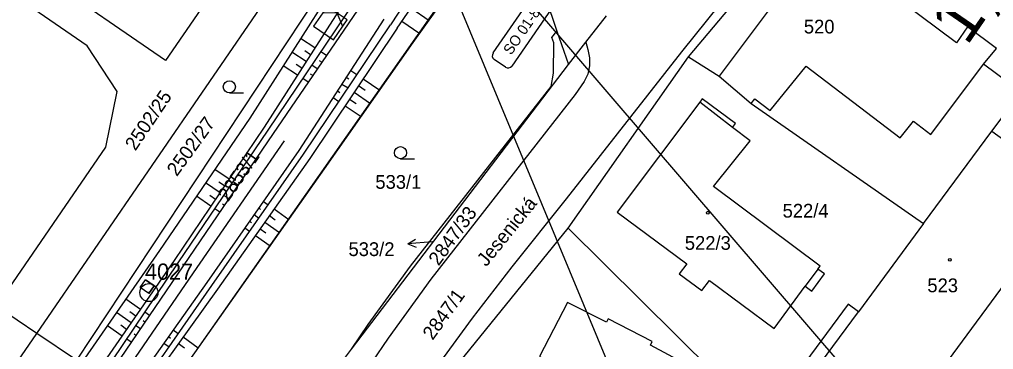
# Model space of a CAD drawing. Extents: x -558358 to -557517, y -1073786 to -1073189.
# Drawn here: x -558199.4 to -558078.9, y -1073467.9 to -1073427.1 of the extents above; entities that cross this region are included whole.
import ezdxf

# ---------------------------------------------------------------- set-up
doc = ezdxf.new("R2010")
doc.units = 0
for name, color, linetype in [('Body', 7, 'Continuous'), ('Hranice parcel', 7, 'Continuous'), ('Kolej', 7, 'Continuous'), ('Křížky', 7, 'Continuous'), ('Lomové body_krizky', 7, 'Continuous'), ('Návěst místo trati', 7, 'Continuous'), ('Parcelní čísla', 7, 'Continuous'), ('Plot - zábradlí', 7, 'Continuous'), ('Pop  PČ popisy', 7, 'Continuous'), ('Přejezd - štěrkové lože', 7, 'Continuous'), ('Sonda - šrafa - vrstevnice', 7, 'Continuous'), ('Svazek obcí údolí Desné', 7, 'Continuous'), ('Vnitřní kresba', 7, 'Continuous'), ('Vrstva 1', 7, 'Continuous'), ('Vrstva 28', 7, 'Continuous'), ('Vrstva 60', 7, 'Continuous'), ('Značky budov', 7, 'Continuous'), ('Značky kultur', 7, 'Continuous')]:
    doc.layers.add(name, color=color, linetype=linetype)

msp = doc.modelspace()

# ---------------------------------------------------------------- linework, layer by layer
at = {"layer": 'Body'}
for p, q in [((-558182.76, -1073460), (-558183.81, -1073459.27)), ((-558183.41, -1073460.95), (-558184.47, -1073460.2))]:
    msp.add_line(p, q, dxfattribs=at)
for points in [[(-558182.76, -1073460), (-558183.41, -1073460.95), (-558184.47, -1073460.2), (-558183.81, -1073459.27), (-558182.76, -1073460)], [(-558184.47, -1073460.2), (-558184.47, -1073460.2), (-558183.81, -1073459.27), (-558183.81, -1073459.27)], [(-558183.41, -1073460.95), (-558183.41, -1073460.95), (-558182.76, -1073460), (-558182.76, -1073460)]]:
    msp.add_lwpolyline(points, dxfattribs=at)
at = {"layer": 'Hranice parcel'}
for p, q in [((-558116.63, -1073431.7), (-558081, -1073389.4)), ((-558138.47, -1073412.32), (-558132.91, -1073428.56)), ((-558197.28, -1073465.89), (-558161.06, -1073413.25)), ((-558100.23, -1073417.28), (-558112.83, -1073434.1)), ((-558129.35, -1073429.91), (-558126.8, -1073426.64)), ((-558133.56, -1073429.34), (-558132.91, -1073428.56)), ((-558132.91, -1073428.56), (-558131.5, -1073432.67)), ((-558131.5, -1073432.67), (-558129.35, -1073429.91)), ((-558129.35, -1073429.91), (-558129.07, -1073430.81)), ((-558131.54, -1073452.88), (-558116.63, -1073431.7)), ((-558116.63, -1073431.7), (-558112.83, -1073434.1)), ((-558158.31, -1073467.84), (-558131.5, -1073432.67)), ((-558087.54, -1073452.3), (-558079.09, -1073440.91)), ((-558079.09, -1073440.91), (-558069.01, -1073448.19)), ((-558087.54, -1073452.3), (-558095.61, -1073463.24)), ((-558111.36, -1073472.82), (-558131.54, -1073452.88)), ((-558197.28, -1073465.89), (-558202.26, -1073462.53)), ((-558158.31, -1073467.84), (-558156.26, -1073464.79)), ((-558192.36, -1073469.21), (-558197.28, -1073465.89)), ((-558164.08, -1073475.42), (-558158.31, -1073467.84))]:
    msp.add_line(p, q, dxfattribs=at)
for points in [[(-558086.19, -1073392.25), (-558100.56, -1073410.01), (-558117.51, -1073431.08), (-558131.78, -1073449.27), (-558138.48, -1073457.68), (-558143.38, -1073464.02), (-558146.99, -1073468.89), (-558150.46, -1073473.83), (-558152.02, -1073476.41), (-558154.26, -1073480.97), (-558156.46, -1073486.6), (-558158.91, -1073494.31), (-558160.3, -1073500.48), (-558162.16, -1073510.4), (-558165.76, -1073536.46), (-558169.94, -1073565.43), (-558173.74, -1073591.61), (-558177.66, -1073620.33), (-558178.51, -1073631.87), (-558179.02, -1073643), (-558179.24, -1073655.12), (-558179.45, -1073666.94), (-558179.49, -1073675.4)], [(-558166.05, -1073409.92), (-558181.36, -1073432.16), (-558196.71, -1073421.6)], [(-558202.26, -1073462.53), (-558188.73, -1073442.87), (-558187.31, -1073436.01), (-558191.04, -1073430.36), (-558216.02, -1073413.17)], [(-558079.09, -1073440.91), (-558075.49, -1073436.06), (-558080.13, -1073432.64), (-558078.53, -1073430.7), (-558082.12, -1073428.01), (-558083.47, -1073429.99), (-558090.26, -1073424.91), (-558087.3, -1073420.92), (-558091.08, -1073418.03), (-558093.98, -1073421.97), (-558100.23, -1073417.28)], [(-558156.26, -1073464.79), (-558151.01, -1073457.58), (-558133.63, -1073435.37), (-558133.35, -1073433.74), (-558133.31, -1073429.98), (-558133.56, -1073429.34)], [(-558129.07, -1073430.81), (-558128.89, -1073431.83), (-558128.89, -1073432.84), (-558129.1, -1073433.85), (-558129.56, -1073434.77), (-558130.67, -1073436.36), (-558148.52, -1073459.19), (-558153.8, -1073466.46), (-558155.8, -1073469.46), (-558158.84, -1073474.63), (-558161.5, -1073480.01), (-558162.64, -1073482.78), (-558164.73, -1073488.39)], [(-558112.83, -1073434.1), (-558108.9, -1073437.49), (-558087.54, -1073452.3)], [(-558115.24, -1073437.31), (-558125.46, -1073450.9), (-558116.85, -1073457.27), (-558117.77, -1073458.51), (-558114.97, -1073460.58), (-558114.05, -1073459.35), (-558106.05, -1073465.28), (-558102.2, -1073460.05)], [(-558110.8, -1073439.94), (-558114.93, -1073436.89), (-558115.24, -1073437.31)], [(-558100.63, -1073457.93), (-558100.36, -1073457.56), (-558113.55, -1073447.75), (-558109, -1073442.11), (-558111.2, -1073440.45), (-558110.8, -1073439.94)], [(-558069.01, -1073448.19), (-558089.39, -1073475.8), (-558089.17, -1073475.95), (-558090.09, -1073477.27), (-558100.29, -1073469.58), (-558095.61, -1073463.24)], [(-558151.25, -1073481.61), (-558144.94, -1073469.39), (-558131.54, -1073452.88)], [(-558102.2, -1073460.05), (-558101.38, -1073460.67), (-558099.8, -1073458.54), (-558100.63, -1073457.93)], [(-558111.36, -1073472.82), (-558111.67, -1073473.41), (-558117.43, -1073469.44), (-558121.34, -1073467.34), (-558121.11, -1073466.9), (-558126.57, -1073464.07), (-558126.8, -1073464.51), (-558131.6, -1073462.08), (-558135.08, -1073468.74), (-558134.91, -1073468.83), (-558142.45, -1073483.25), (-558143.96, -1073486.09)], [(-558095.61, -1073463.24), (-558096.89, -1073462.29), (-558107.49, -1073476.62)], [(-558235.03, -1073522.1), (-558231.61, -1073515.78), (-558197.28, -1073465.89)]]:
    msp.add_lwpolyline(points, dxfattribs=at)
at = {"layer": 'Kolej'}
msp.add_lwpolyline([(-558222.5, -1073523.52), (-558211.35, -1073507.26), (-558189.16, -1073474.89), (-558177.86, -1073458.42), (-558166.63, -1073442.09)], dxfattribs=at)
at = {"layer": 'Křížky'}
for points in [[(-558140.82, -1073431.24), (-558135.04, -1073422.86)], [(-558132.71, -1073424.46), (-558138.49, -1073432.85)], [(-558139.28, -1073432.99), (-558140.67, -1073432.03)]]:
    msp.add_lwpolyline(points, dxfattribs=at)
for centre, start, end in [((-558140.35, -1073431.57), 145.4427, 235.4427), ((-558138.96, -1073432.53), 235.4427, 325.4427)]:
    msp.add_arc(centre, 0.566, start, end, dxfattribs=at)
at = {"layer": 'Lomové body_krizky'}
for points in [[(-558152.7, -1073428.17), (-558144.23, -1073415.84), (-558139.35, -1073410.55), (-558136.98, -1073416.27)], [(-558160.27, -1073422.61), (-558170.92, -1073439.28), (-558182.07, -1073455.63), (-558193.45, -1073472.04), (-558204.95, -1073487.53), (-558215.83, -1073504.11), (-558218.74, -1073509.41), (-558221.47, -1073511.54)], [(-558158.61, -1073423.97), (-558169.15, -1073440.42), (-558180.26, -1073456.88), (-558191.27, -1073472.78), (-558202.46, -1073489.11), (-558213.8, -1073505.71), (-558218.06, -1073510.9), (-558220.02, -1073511.36), (-558220.66, -1073512.06)], [(-558152.7, -1073428.17), (-558163.49, -1073444.26), (-558174.92, -1073460.4), (-558186.51, -1073476.58), (-558197.24, -1073492.86), (-558208.77, -1073509.05), (-558219.85, -1073525.27), (-558227.1, -1073535.75), (-558230.39, -1073540.52), (-558231, -1073543.03)]]:
    msp.add_lwpolyline(points, dxfattribs=at)
at = {"layer": 'Návěst místo trati'}
for points in [[(-558160.09, -1073426.3), (-558161.32, -1073425.45), (-558163.02, -1073427.92), (-558160.55, -1073429.62), (-558158.85, -1073427.15), (-558160.09, -1073426.3)], [(-558159.42, -1073427.97), (-558160.09, -1073426.3), (-558161.89, -1073426.27)]]:
    msp.add_lwpolyline(points, dxfattribs=at)
at = {"layer": 'Plot - zábradlí'}
for points in [[(-558150.68, -1073429.95), (-558139.41, -1073414.15), (-558135.83, -1073423.84)], [(-558226.6, -1073552.39), (-558229.62, -1073542.12), (-558228.84, -1073541.34), (-558220.94, -1073529.81), (-558210.66, -1073515.21), (-558195.56, -1073493.62), (-558184.31, -1073477.57), (-558177.73, -1073468.27), (-558161.67, -1073445.55), (-558150.68, -1073429.95)]]:
    msp.add_lwpolyline(points, dxfattribs=at)
at = {"layer": 'Pop  PČ popisy'}
for p, q in [((-558151.36, -1073454.83), (-558150.41, -1073454.25)), ((-558148.37, -1073454.57), (-558151.36, -1073454.83)), ((-558151.36, -1073454.83), (-558150.32, -1073455.24))]:
    msp.add_line(p, q, dxfattribs=at)
at = {"layer": 'Přejezd - štěrkové lože'}
for p, q in [((-558161.43, -1073431.55), (-558162.11, -1073431.09)), ((-558162.56, -1073433.2), (-558163.23, -1073432.75)), ((-558162, -1073432.38), (-558162.27, -1073432.19)), ((-558163.13, -1073434.02), (-558163.39, -1073433.84)), ((-558158.97, -1073434.24), (-558158.67, -1073434.44)), ((-558158.43, -1073433.4), (-558157.65, -1073433.91)), ((-558163.69, -1073434.85), (-558164.35, -1073434.4)), ((-558159.52, -1073435.08), (-558158.76, -1073435.56)), ((-558160.06, -1073435.92), (-558159.77, -1073436.11)), ((-558160.61, -1073436.75), (-558159.88, -1073437.23)), ((-558172.38, -1073447.59), (-558172.99, -1073447.17)), ((-558172.94, -1073448.42), (-558173.19, -1073448.25)), ((-558174.06, -1073450.07), (-558174.31, -1073449.91)), ((-558173.5, -1073449.24), (-558174.11, -1073448.83)), ((-558169.23, -1073449.57), (-558168.64, -1073449.99)), ((-558174.62, -1073450.9), (-558175.23, -1073450.48)), ((-558169.81, -1073450.39), (-558169.57, -1073450.56)), ((-558170.95, -1073452.03), (-558170.71, -1073452.2)), ((-558170.38, -1073451.21), (-558169.78, -1073451.63)), ((-558171.52, -1073452.85), (-558170.93, -1073453.27)), ((-558183.88, -1073464.5), (-558184.11, -1073464.34)), ((-558183.32, -1073463.67), (-558183.9, -1073463.28)), ((-558184.45, -1073465.32), (-558185.02, -1073464.93)), ((-558180.39, -1073465.46), (-558179.76, -1073465.91)), ((-558185.58, -1073466.97), (-558186.14, -1073466.59)), ((-558185.01, -1073466.15), (-558185.24, -1073465.99)), ((-558180.96, -1073466.27), (-558180.71, -1073466.46)), ((-558181.54, -1073467.09), (-558180.9, -1073467.54))]:
    msp.add_line(p, q, dxfattribs=at)
for points in [[(-558140.88, -1073407.43), (-558141.3, -1073409.14), (-558145.29, -1073415.26), (-558153.52, -1073427.77)], [(-558233.12, -1073536.27), (-558231.44, -1073532.59), (-558224.31, -1073522.11), (-558213.32, -1073506.02), (-558201.98, -1073489.48), (-558190.68, -1073473.3), (-558179.76, -1073457.16), (-558168.65, -1073440.76), (-558157.79, -1073424.72)], [(-558157.06, -1073425.16), (-558168.03, -1073441.18), (-558179.14, -1073457.55), (-558190.46, -1073474.12), (-558201.29, -1073490), (-558212.69, -1073506.36), (-558223.92, -1073522.5), (-558230.65, -1073533.02), (-558233.12, -1073536.27)], [(-558154.33, -1073427.06), (-558164.84, -1073443.28), (-558176.23, -1073459.59), (-558187.79, -1073475.9), (-558198.67, -1073491.89), (-558209.91, -1073508.33), (-558221.19, -1073524.36), (-558228.27, -1073535), (-558231.51, -1073539.54)], [(-558231.51, -1073539.54), (-558230.18, -1073538.97), (-558227.65, -1073535.49), (-558220.31, -1073524.95), (-558209.15, -1073508.87), (-558197.9, -1073492.46), (-558187.04, -1073476.34), (-558175.63, -1073459.98), (-558164.25, -1073443.72), (-558153.52, -1073427.77)]]:
    msp.add_lwpolyline(points, dxfattribs=at)
at = {"layer": 'Sonda - šrafa - vrstevnice'}
for p, q in [((-558150.97, -1073425.66), (-558148.72, -1073427.21)), ((-558152.1, -1073427.31), (-558149.89, -1073428.83)), ((-558162.86, -1073430.61), (-558164.65, -1073429.46)), ((-558163.94, -1073432.29), (-558165.72, -1073431.15)), ((-558163.4, -1073431.45), (-558164.11, -1073430.99)), ((-558165.02, -1073433.98), (-558166.8, -1073432.83)), ((-558164.48, -1073433.13), (-558165.19, -1073432.68)), ((-558157.45, -1073435.27), (-558156.63, -1073435.82)), ((-558156.9, -1073434.43), (-558154.82, -1073435.82)), ((-558158.01, -1073436.09), (-558155.97, -1073437.46)), ((-558159.12, -1073437.76), (-558157.12, -1073439.1)), ((-558158.57, -1073436.93), (-558157.76, -1073437.47)), ((-558173.48, -1073446.84), (-558175.26, -1073445.64)), ((-558174.6, -1073448.5), (-558176.38, -1073447.29)), ((-558174.04, -1073447.67), (-558174.75, -1073447.19)), ((-558175.72, -1073450.15), (-558177.51, -1073448.94)), ((-558175.16, -1073449.33), (-558175.87, -1073448.84)), ((-558167.91, -1073450.5), (-558166.08, -1073451.8)), ((-558169.07, -1073452.14), (-558167.24, -1073453.43)), ((-558168.49, -1073451.32), (-558167.76, -1073451.84)), ((-558169.65, -1073452.95), (-558168.91, -1073453.47)), ((-558170.22, -1073453.77), (-558168.39, -1073455.06)), ((-558184.44, -1073462.92), (-558186.26, -1073461.66)), ((-558185.01, -1073463.74), (-558185.74, -1073463.24)), ((-558185.58, -1073464.56), (-558187.4, -1073463.3)), ((-558186.71, -1073466.21), (-558188.54, -1073464.95)), ((-558186.15, -1073465.39), (-558186.88, -1073464.88)), ((-558179.16, -1073466.32), (-558177.3, -1073467.66)), ((-558179.74, -1073467.13), (-558179, -1073467.67))]:
    msp.add_line(p, q, dxfattribs=at)
at = {"layer": 'Svazek obcí údolí Desné'}
for p, q in [((-558138.47, -1073412.32), (-558177.75, -1073468.29)), ((-558157.08, -1073415.91), (-558192.36, -1073469.21))]:
    msp.add_line(p, q, dxfattribs=at)
at = {"layer": 'Vnitřní kresba'}
for p, q in [((-558106.53, -1073438.34), (-558102.09, -1073432.87)), ((-558102.09, -1073432.87), (-558090.44, -1073441.72)), ((-558086.64, -1073441.31), (-558080.13, -1073432.64)), ((-558111.2, -1073440.45), (-558115.24, -1073437.31)), ((-558108.9, -1073437.49), (-558108.41, -1073436.89)), ((-558108.41, -1073436.89), (-558106.53, -1073438.34)), ((-558090.44, -1073441.72), (-558088.8, -1073439.66)), ((-558088.8, -1073439.66), (-558086.64, -1073441.31)), ((-558100.63, -1073457.93), (-558102.2, -1073460.05))]:
    msp.add_line(p, q, dxfattribs=at)
at = {"layer": 'Vrstva 28'}
for p, q in [((-558150.5, -1073408.33), (-557941.76, -1073651.48)), ((-558150.16, -1073413.05), (-558044.9, -1073665.43))]:
    msp.add_line(p, q, dxfattribs=at)
at = {"layer": 'Vrstva 60'}
msp.add_line((-558183.4, -1073460.84), (-558183.4, -1073460.84), dxfattribs=at)
msp.add_line((-558183.4, -1073460.84), (-558183.4, -1073460.84), dxfattribs=at)
for radius in [1.12, 1.12, 0.045, 0.045]:
    msp.add_circle((-558183.4, -1073460.84), radius, dxfattribs=at)
at = {"layer": 'Značky budov'}
for centre in [(-558114.25, -1073450.97), (-558084.29, -1073456.8)]:
    msp.add_circle(centre, 0.175, dxfattribs=at)
at = {"layer": 'Značky kultur'}
for p, q in [((-558173.44, -1073436.18), (-558171.69, -1073436.18)), ((-558152.27, -1073444.31), (-558150.52, -1073444.31))]:
    msp.add_line(p, q, dxfattribs=at)
for centre in [(-558173.44, -1073435.43), (-558152.27, -1073443.56)]:
    msp.add_circle(centre, 0.75, dxfattribs=at)

# ---------------------------------------------------------------- texts
at = {"layer": 'Křížky'}
msp.add_text('SO 01-86-04', height=1.2994, rotation=55.4427, dxfattribs=at).set_placement((-558138.58, -1073431.58))
at = {"layer": 'Návěst místo trati'}
msp.add_text('1,6', height=6, rotation=55.5139, dxfattribs=at).set_placement((-558082.19, -1073430.47))
at = {"layer": 'Parcelní čísla'}
for s, p in [('520', (-558102.36, -1073428.83)), ('533/1', (-558155.38, -1073448.02)), ('522/4', (-558104.99, -1073451.58)), ('533/2', (-558158.7, -1073456.33)), ('522/3', (-558117.09, -1073455.56)), ('523', (-558087.08, -1073460.8))]:
    msp.add_text(s, height=1.7, dxfattribs=at).set_placement(p)
for s, rotation, p in [('2502/25', 56, (-558185.07, -1073443.42)), ('2502/27', 54, (-558179.94, -1073446.58)), ('2847/33', 54, (-558147.56, -1073457.63)), ('2847/1', 54, (-558148.29, -1073466.81))]:
    msp.add_text(s, height=1.7, rotation=rotation, dxfattribs=at).set_placement(p)
at = {"layer": 'Pop  PČ popisy'}
msp.add_text('Jesenická', height=1.7, rotation=51, dxfattribs=at).set_placement((-558141.65, -1073457.73))
at = {"layer": 'Vrstva 1'}
msp.add_text('2853/1', height=1.7, rotation=55, dxfattribs=at).set_placement((-558173.6, -1073449.7))
at = {"layer": 'Vrstva 60'}
msp.add_text('4027', height=2, dxfattribs=at).set_placement((-558183.88, -1073459.25))

doc.saveas('drawing.dxf')
